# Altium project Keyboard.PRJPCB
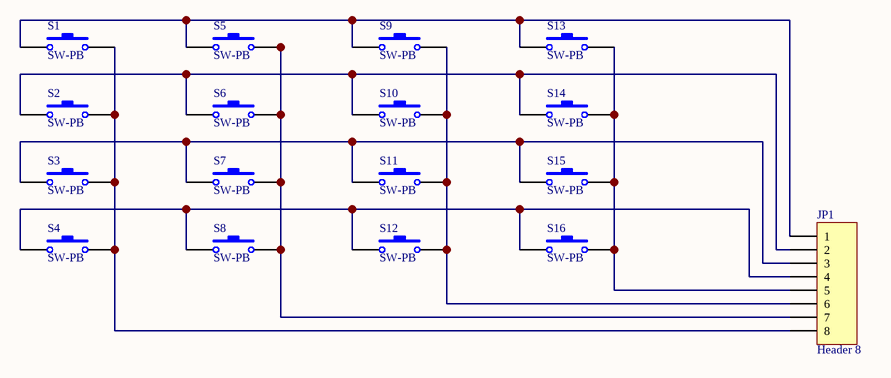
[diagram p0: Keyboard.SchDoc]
1 sheet, 17 parts. Net scope: global (net labels, ports and power ports of the same name join across sheets).
Board file: Keyboard.PCBDOC

## Sheet Keyboard.SchDoc
size B

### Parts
JP1  Header 8  [HDR1X8]
S1  SW-PB  [SPST-2]
S2  SW-PB  [SPST-2]
S3  SW-PB  [SPST-2]
S4  SW-PB  [SPST-2]
S5  SW-PB  [SPST-2]
S6  SW-PB  [SPST-2]
S7  SW-PB  [SPST-2]
S8  SW-PB  [SPST-2]
S9  SW-PB  [SPST-2]
S10  SW-PB  [SPST-2]
S11  SW-PB  [SPST-2]
S12  SW-PB  [SPST-2]
S13  SW-PB  [SPST-2]
S14  SW-PB  [SPST-2]
S15  SW-PB  [SPST-2]
S16  SW-PB  [SPST-2]

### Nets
NetJP1_1: JP1.1 S1.1 S5.1 S9.1 S13.1
NetJP1_2: JP1.2 S2.1 S6.1 S10.1 S14.1
NetJP1_3: JP1.3 S3.1 S7.1 S11.1 S15.1
NetJP1_4: JP1.4 S4.1 S8.1 S12.1 S16.1
NetJP1_5: JP1.5 S13.2 S14.2 S15.2 S16.2
NetJP1_6: JP1.6 S9.2 S10.2 S11.2 S12.2
NetJP1_7: JP1.7 S5.2 S6.2 S7.2 S8.2
NetJP1_8: JP1.8 S1.2 S2.2 S3.2 S4.2

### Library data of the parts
JP1 = Header 8: Header, 8-Pin; Manufacturer: Generic Components; Class I: Connector
S1-S16 = SW-PB: Switch; Manufacturer: Generic Components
